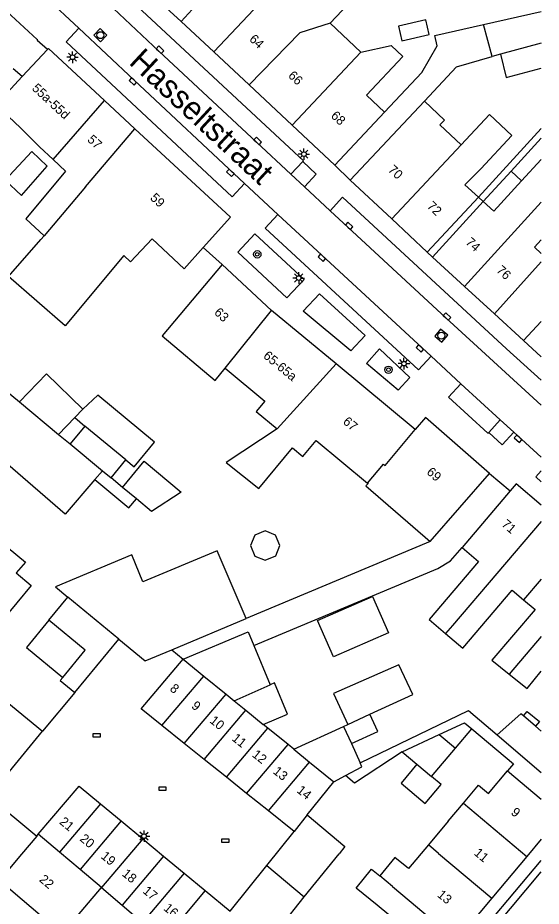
# Model space of a CAD drawing. Extents: x 132573 to 132944, y 398226 to 398676.
# Drawn here: x 132883.4 to 132940.1, y 398341.8 to 398438.1 of the extents above; entities that cross this region are included whole.
import ezdxf

# ---------------------------------------------------------------- set-up
doc = ezdxf.new("R2010")
doc.units = 0
for name, color, linetype in [('gg-afsc-erfafscheiding', 7, 'Continuous'), ('gg-afsc-hekwerk', 7, 'Continuous'), ('gg-afsc-muur', 7, 'Continuous'), ('gg-anno-huisnummerreeks BGT', 7, 'Continuous'), ('gg-anno-openbare ruimte label', 7, 'Continuous'), ('gg-bbg-bijgebouw', 7, 'Continuous'), ('gg-bbg-gedigitaliseerde bebouwing', 7, 'Continuous'), ('gg-bbg-gedigitaliseerde bebouwing onder overbouw', 7, 'Continuous'), ('gg-bbg-gedigitaliseerde bijgebouw', 7, 'Continuous'), ('gg-bbg-gedigitaliseerde overbouw', 7, 'Continuous'), ('gg-bbg-hoofdgebouw', 7, 'Continuous'), ('gg-bbg-luifel en loopbrug', 7, 'Continuous'), ('gg-bbg-pand overbouw', 7, 'Continuous'), ('gg-bbg-tussenscheiding', 7, 'Continuous'), ('gg-knt-verharding', 7, 'Continuous'), ('gg-knt-verharding nz', 7, 'Continuous'), ('gt-bbg-plantopografie pand', 7, 'Continuous'), ('gt-symb-boom', 7, 'Continuous'), ('gt-symb-kolk', 7, 'Continuous'), ('gt-symb-kolk center center', 7, 'Continuous'), ('gt-symb-lichtmast', 7, 'Continuous'), ('gt-symb-rioolschacht', 7, 'Continuous')]:
    doc.layers.add(name, color=color, linetype=linetype)

msp = doc.modelspace()

# ---------------------------------------------------------------- linework, layer by layer
at = {"layer": 'gg-afsc-erfafscheiding'}
for p, q in [((132933.304, 398418.624), (132940.113, 398426.079)), ((132936.851, 398421.461), (132940.113, 398425.032)), ((132928.09, 398381.331), (132908.172, 398372.976))]:
    msp.add_line(p, q, dxfattribs=at)
for points in [[(132923.154, 398427.841), (132927.189, 398432.136), (132928.845, 398435.01), (132928.603, 398436.147), (132933.873, 398437.331)], [(132927.46, 398429.034), (132930.944, 398432.75), (132934.814, 398433.88)], [(132863.045, 398395.109), (132866.966, 398391.729), (132867.783, 398392.696), (132884.262, 398379.11), (132883.243, 398377.928)], [(132908.987, 398370.064), (132928.905, 398378.419), (132930.304, 398379.226), (132931.543, 398380.683)], [(132920.514, 398357.346), (132932.24, 398363.01), (132935.33, 398360.377)], [(132932.583, 398361.056), (132937.101, 398357.264), (132936.459, 398356.498)], [(132925.064, 398358.538), (132919.898, 398355.166), (132918.925, 398355.982)]]:
    msp.add_lwpolyline(points, dxfattribs=at)
at = {"layer": 'gg-afsc-hekwerk'}
for p, q in [((132883.894, 398431.693), (132882.94, 398432.54)), ((132917.75, 398422.09), (132919.44, 398420.47)), ((132903.499, 398413.169), (132905.55, 398411.33))]:
    msp.add_line(p, q, dxfattribs=at)
at = {"layer": 'gg-afsc-muur'}
for p, q in [((132900.101, 398369.589), (132901.34, 398368.58)), ((132889.61, 398364.96), (132886.1, 398360.77))]:
    msp.add_line(p, q, dxfattribs=at)
at = {"layer": 'gg-bbg-bijgebouw'}
for p, q in [((132889.61, 398364.96), (132894.37, 398370.74)), ((132888.02, 398366.27), (132889.61, 398364.96)), ((132901.457, 398359.449), (132899.027, 398361.398)), ((132903.597, 398357.733), (132901.457, 398359.449)), ((132906.021, 398355.789), (132903.597, 398357.733)), ((132908.204, 398354.038), (132906.021, 398355.789)), ((132910.56, 398352.149), (132908.204, 398354.038)), ((132892.386, 398352.921), (132894.632, 398351.059)), ((132913.34, 398349.92), (132910.56, 398352.149)), ((132894.632, 398351.059), (132896.957, 398349.133)), ((132896.957, 398349.133), (132899.215, 398347.261)), ((132910.388, 398346.238), (132913.34, 398349.92)), ((132899.215, 398347.261), (132901.448, 398345.411)), ((132906.42, 398341.29), (132910.388, 398346.238)), ((132901.448, 398345.411), (132903.731, 398343.519)), ((132903.731, 398343.519), (132906.42, 398341.29))]:
    msp.add_line(p, q, dxfattribs=at)
for points in [[(132905.024, 398380.33), (132896.986, 398376.973), (132895.765, 398379.898), (132887.523, 398376.409), (132888.847, 398375.287)], [(132894.37, 398370.74), (132897.235, 398368.405), (132900.101, 398369.589)], [(132899.027, 398361.398), (132896.78, 398363.2), (132901.34, 398368.58)], [(132885.652, 398349.619), (132890.07, 398354.84), (132892.386, 398352.921)]]:
    msp.add_lwpolyline(points, dxfattribs=at)
at = {"layer": 'gg-bbg-gedigitaliseerde bebouwing'}
for p, q in [((132917.26, 398437.467), (132920.68, 398441.107)), ((132917.26, 398437.467), (132920.587, 398434.341)), ((132927.46, 398429.034), (132919.44, 398420.47)), ((132923.154, 398427.841), (132917.75, 398422.09)), ((132883.711, 398426.159), (132885.768, 398424.097)), ((132885.768, 398424.097), (132887.253, 398422.718)), ((132937.984, 398420.392), (132940.113, 398422.719)), ((132884.293, 398416.301), (132886.268, 398414.459)), ((132885.915, 398414.043), (132886.268, 398414.459)), ((132901.436, 398410.869), (132903.499, 398413.169)), ((132928.09, 398381.331), (132934.52, 398388.7)), ((132936.749, 398386.804), (132931.543, 398380.683)), ((132938.208, 398375.004), (132939.439, 398373.954)), ((132927.971, 398372.874), (132929.758, 398371.352)), ((132929.758, 398371.352), (132931.616, 398369.768)), ((132880.436, 398365.438), (132886.1, 398360.77)), ((132936.459, 398356.498), (132940.113, 398353.426)), ((132930.038, 398351.024), (132931.684, 398352.988)), ((132930.038, 398351.024), (132927.894, 398348.466)), ((132888.246, 398338.849), (132892.476, 398343.845))]:
    msp.add_line(p, q, dxfattribs=at)
for points in [[(132920.587, 398434.341), (132923.848, 398435.076), (132925.114, 398433.886), (132921.179, 398429.697), (132923.154, 398427.841)], [(132883.894, 398431.693), (132881.052, 398428.627), (132883.711, 398426.159)], [(132931.431, 398424.31), (132929.142, 398426.452), (132929.644, 398426.989), (132927.46, 398429.034)], [(132933.304, 398418.624), (132931.825, 398419.979), (132933.559, 398421.711), (132936.939, 398425.322), (132934.508, 398427.597), (132931.431, 398424.31)], [(132887.253, 398422.718), (132888.6, 398421.466), (132884.293, 398416.301)], [(132933.825, 398418.147), (132934.97, 398417.098), (132937.984, 398420.392)], [(132901.436, 398410.869), (132897.968, 398414.103), (132895.649, 398411.617), (132894.918, 398412.299), (132888.54, 398404.712), (132882.424, 398410.022), (132885.915, 398414.043)], [(132940.113, 398414.016), (132939.381, 398413.216), (132940.113, 398412.546)], [(132905.55, 398411.33), (132899.05, 398403.625), (132904.804, 398398.771), (132905.877, 398400.107)], [(132905.877, 398400.107), (132910.183, 398396.551), (132909.246, 398395.417), (132911.533, 398393.528)], [(132911.533, 398393.528), (132905.999, 398389.897), (132909.53, 398387.07), (132913.173, 398391.479), (132914.312, 398390.538), (132915.742, 398392.268), (132921.306, 398387.669)], [(132921.306, 398387.669), (132921.356, 398387.628), (132921.124, 398387.363), (132928.09, 398381.331)], [(132931.543, 398380.683), (132933.329, 398379.161), (132927.971, 398372.874)], [(132931.616, 398369.768), (132936.976, 398376.054), (132938.208, 398375.004)], [(132939.439, 398373.954), (132934.769, 398368.474), (132936.647, 398366.973)], [(132936.647, 398366.973), (132938.6, 398365.412), (132940.113, 398367.305)], [(132931.684, 398352.988), (132933.33, 398354.951), (132934.406, 398354.049), (132936.459, 398356.498)], [(132927.894, 398348.466), (132925.75, 398345.907), (132924.242, 398347.118), (132922.637, 398345.115)], [(132922.348, 398341.957), (132920.069, 398343.785), (132921.723, 398345.848), (132922.637, 398345.115)], [(132920.77, 398337.534), (132923.599, 398340.908), (132922.348, 398341.957)]]:
    msp.add_lwpolyline(points, dxfattribs=at)
at = {"layer": 'gg-bbg-gedigitaliseerde bebouwing onder overbouw'}
for p, q in [((132927.76, 398412.69), (132933.304, 398418.624)), ((132928.33, 398412.13), (132933.825, 398418.147))]:
    msp.add_line(p, q, dxfattribs=at)
at = {"layer": 'gg-bbg-gedigitaliseerde bijgebouw'}
for p, q in [((132933.873, 398437.331), (132940.113, 398438.728)), ((132934.814, 398433.88), (132933.873, 398437.331)), ((132940.113, 398435.305), (132935.71, 398434.121)), ((132935.71, 398434.121), (132934.814, 398433.88)), ((132889.588, 398394.748), (132890.488, 398395.682)), ((132887.849, 398392.941), (132889.588, 398394.748)), ((132890.695, 398393.832), (132889.102, 398391.905)), ((132895.126, 398390.166), (132890.695, 398393.832)), ((132887.849, 398392.941), (132889.102, 398391.905)), ((132893.532, 398388.24), (132895.126, 398390.166)), ((132894.778, 398387.198), (132893.532, 398388.24)), ((132908.172, 398372.976), (132905.024, 398380.33)), ((132886.805, 398372.807), (132888.847, 398375.287)), ((132900.101, 398369.589), (132908.172, 398372.976)), ((132908.987, 398370.064), (132910.77, 398365.813)), ((132888.02, 398366.27), (132888.292, 398366.601)), ((132917.616, 398364.862), (132919.158, 398361.509)), ((132937.913, 398362.669), (132935.33, 398360.377)), ((132938.182, 398362.44), (132937.913, 398362.669)), ((132939.49, 398361.326), (132938.182, 398362.44)), ((132910.523, 398361.1), (132910.015, 398361.514)), ((132912.692, 398359.333), (132910.523, 398361.1)), ((132913.317, 398358.824), (132918.698, 398361.298)), ((132918.698, 398361.298), (132919.158, 398361.509)), ((132940.113, 398360.795), (132939.49, 398361.326)), ((132925.064, 398358.538), (132929.071, 398360.418)), ((132929.071, 398360.418), (132930.815, 398358.952)), ((132935.33, 398360.377), (132940.113, 398356.302)), ((132913.317, 398358.824), (132912.692, 398359.333)), ((132919.554, 398359.436), (132920.514, 398357.346)), ((132928.23, 398355.877), (132930.815, 398358.952)), ((132925.064, 398358.538), (132926.647, 398357.208)), ((132917.65, 398355.295), (132918.925, 398355.982)), ((132914.774, 398351.708), (132917.65, 398355.295)), ((132914.457, 398342.827), (132918.217, 398347.516)), ((132892.476, 398343.845), (132894.719, 398341.948)), ((132910.008, 398337.28), (132914.457, 398342.827)), ((132894.719, 398341.948), (132896.932, 398340.075))]:
    msp.add_line(p, q, dxfattribs=at)
for points in [[(132925.01, 398435.572), (132927.985, 398436.257), (132927.62, 398437.841), (132924.646, 398437.156), (132925.01, 398435.572)], [(132890.488, 398395.682), (132886.533, 398399.49), (132883.608, 398396.451)], [(132891.771, 398388.035), (132888.559, 398384.309), (132876.639, 398394.585), (132880.479, 398399.04), (132883.608, 398396.451)], [(132894.778, 398387.198), (132897.114, 398390.025), (132901.104, 398386.685), (132897.901, 398384.584), (132896.279, 398385.941)], [(132891.771, 398388.035), (132895.461, 398384.964), (132896.279, 398385.941)], [(132910.211, 398382.49), (132909.085, 398382.016), (132908.623, 398380.884), (132909.097, 398379.757), (132910.229, 398379.296), (132911.355, 398379.77), (132911.817, 398380.901), (132911.343, 398382.028), (132910.211, 398382.49)], [(132883.243, 398377.928), (132884.878, 398376.579), (132881.764, 398372.802), (132879.522, 398374.651), (132880.633, 398375.999)], [(132888.292, 398366.601), (132890.737, 398369.569), (132886.805, 398372.807)], [(132901.34, 398368.58), (132908.372, 398371.53), (132908.987, 398370.064)], [(132921.559, 398362.613), (132926.2, 398364.747), (132924.71, 398367.986), (132917.616, 398364.862)], [(132910.015, 398361.514), (132912.649, 398362.619), (132911.225, 398366.013), (132910.77, 398365.813)], [(132919.554, 398359.436), (132922.414, 398360.751), (132921.559, 398362.613)], [(132918.925, 398355.982), (132920.702, 398356.939), (132920.514, 398357.346)], [(132926.647, 398357.208), (132924.929, 398355.164), (132927.547, 398352.963), (132929.265, 398355.007), (132928.23, 398355.877)], [(132914.774, 398351.708), (132918.843, 398348.296), (132918.217, 398347.516)]]:
    msp.add_lwpolyline(points, dxfattribs=at)
at = {"layer": 'gg-bbg-gedigitaliseerde overbouw'}
msp.add_line((132933.304, 398418.624), (132933.825, 398418.147), dxfattribs=at)
at = {"layer": 'gg-bbg-hoofdgebouw'}
for p, q in [((132897.465, 398441.015), (132901.114, 398437.654)), ((132901.114, 398437.654), (132904.67, 398434.38)), ((132886.627, 398434.629), (132883.894, 398431.693)), ((132886.74, 398434.75), (132886.627, 398434.629)), ((132892.835, 398429.094), (132886.74, 398434.75)), ((132904.67, 398434.38), (132908.492, 398430.789)), ((132908.492, 398430.789), (132913.143, 398426.419)), ((132896.113, 398426.052), (132892.835, 398429.094)), ((132913.143, 398426.419), (132917.75, 398422.09)), ((132896.113, 398426.052), (132906.45, 398416.46)), ((132919.44, 398420.47), (132923.919, 398416.282)), ((132906.45, 398416.46), (132903.499, 398413.169)), ((132923.919, 398416.282), (132927.76, 398412.69)), ((132931.816, 398408.942), (132928.33, 398412.13)), ((132910.89, 398406.35), (132905.55, 398411.33)), ((132935.049, 398405.985), (132931.816, 398408.942)), ((132917.889, 398400.569), (132910.89, 398406.35)), ((132938.208, 398403.096), (132935.049, 398405.985)), ((132940.113, 398401.353), (132938.208, 398403.096)), ((132926.47, 398393.48), (132917.889, 398400.569)), ((132880.35, 398353.8), (132886.1, 398360.77)), ((132885.477, 398349.412), (132883.843, 398347.481)), ((132885.477, 398349.412), (132885.652, 398349.619)), ((132940.113, 398349.08), (132938.559, 398347.225)), ((132883.843, 398347.481), (132881.424, 398344.622)), ((132938.559, 398347.225), (132934.77, 398342.704)), ((132934.77, 398342.704), (132930.949, 398338.146))]:
    msp.add_line(p, q, dxfattribs=at)
for points in [[(132934.52, 398388.7), (132927.58, 398394.75), (132926.47, 398393.48)], [(132940.113, 398385.259), (132937.4, 398387.57), (132936.749, 398386.804)]]:
    msp.add_lwpolyline(points, dxfattribs=at)
at = {"layer": 'gg-bbg-luifel en loopbrug'}
for p, q in [((132933.825, 398418.147), (132936.851, 398421.461)), ((132936.851, 398421.461), (132937.984, 398420.392)), ((132889.588, 398394.748), (132890.695, 398393.832)), ((132930.815, 398358.952), (132932.583, 398361.056))]:
    msp.add_line(p, q, dxfattribs=at)
for points in [[(132935.71, 398434.121), (132936.33, 398431.578), (132940.113, 398432.596)], [(132884.933, 398423.571), (132882.053, 398420.469), (132883.835, 398418.814), (132886.624, 398422), (132884.933, 398423.571)], [(132895.126, 398390.166), (132896.03, 398389.418), (132898.249, 398392.1), (132892.105, 398397.183), (132890.488, 398395.682)], [(132886.805, 398372.807), (132884.361, 398369.839), (132888.292, 398366.601)], [(132938.182, 398362.44), (132938.603, 398362.935), (132939.911, 398361.821), (132939.49, 398361.326)], [(132929.071, 398360.418), (132931.812, 398361.704), (132932.583, 398361.056)]]:
    msp.add_lwpolyline(points, dxfattribs=at)
at = {"layer": 'gg-bbg-pand overbouw'}
msp.add_line((132928.33, 398412.13), (132927.76, 398412.69), dxfattribs=at)
at = {"layer": 'gg-bbg-tussenscheiding'}
for p, q in [((132904.67, 398434.38), (132915.701, 398446.125)), ((132906.296, 398443.344), (132901.114, 398437.654)), ((132913.143, 398426.419), (132920.587, 398434.341)), ((132887.253, 398422.718), (132892.835, 398429.094)), ((132890.773, 398419.764), (132896.113, 398426.052)), ((132923.919, 398416.282), (132931.431, 398424.31)), ((132890.773, 398419.764), (132886.268, 398414.459)), ((132931.816, 398408.942), (132940.113, 398418.089)), ((132935.049, 398405.985), (132940.113, 398411.628)), ((132905.877, 398400.107), (132910.89, 398406.35)), ((132938.208, 398403.096), (132940.113, 398405.178)), ((132911.533, 398393.528), (132917.889, 398400.569)), ((132883.608, 398396.451), (132887.849, 398392.941)), ((132889.102, 398391.905), (132892.607, 398389.005)), ((132892.607, 398389.005), (132891.771, 398388.035)), ((132892.607, 398389.005), (132893.532, 398388.24)), ((132896.279, 398385.941), (132894.778, 398387.198)), ((132940.113, 398383.507), (132930.494, 398372.216)), ((132940.113, 398377.238), (132938.208, 398375.004)), ((132894.37, 398370.74), (132888.847, 398375.287)), ((132930.494, 398372.216), (132929.758, 398371.352)), ((132940.113, 398371.037), (132936.647, 398366.973)), ((132901.34, 398368.58), (132903.573, 398366.761)), ((132899.027, 398361.398), (132903.573, 398366.761)), ((132903.573, 398366.761), (132905.988, 398364.794)), ((132906.852, 398364.09), (132910.77, 398365.813)), ((132901.457, 398359.449), (132905.988, 398364.794)), ((132905.988, 398364.794), (132906.852, 398364.09)), ((132906.852, 398364.09), (132908.114, 398363.062)), ((132903.597, 398357.733), (132908.114, 398363.062)), ((132908.114, 398363.062), (132910.015, 398361.514)), ((132919.158, 398361.509), (132921.559, 398362.613)), ((132906.021, 398355.789), (132910.523, 398361.1)), ((132918.698, 398361.298), (132919.554, 398359.436)), ((132908.204, 398354.038), (132912.692, 398359.333)), ((132913.317, 398358.824), (132915.033, 398357.426)), ((132910.56, 398352.149), (132915.033, 398357.426)), ((132915.033, 398357.426), (132917.65, 398355.295)), ((132926.647, 398357.208), (132928.23, 398355.877)), ((132931.684, 398352.988), (132938.559, 398347.225)), ((132892.386, 398352.921), (132887.948, 398347.677)), ((132894.632, 398351.059), (132890.175, 398345.792)), ((132914.774, 398351.708), (132913.34, 398349.92)), ((132887.948, 398347.677), (132885.652, 398349.619)), ((132896.957, 398349.133), (132892.476, 398343.845)), ((132928.982, 398347.554), (132927.894, 398348.466)), ((132890.175, 398345.792), (132887.948, 398347.677)), ((132899.215, 398347.261), (132894.719, 398341.948)), ((132928.982, 398347.554), (132934.77, 398342.704)), ((132910.388, 398346.238), (132914.457, 398342.827)), ((132892.476, 398343.845), (132890.175, 398345.792)), ((132901.448, 398345.411), (132896.932, 398340.075)), ((132888.246, 398338.849), (132881.424, 398344.622)), ((132924.022, 398343.954), (132922.637, 398345.115)), ((132903.731, 398343.519), (132899.196, 398338.16)), ((132924.022, 398343.954), (132930.949, 398338.146))]:
    msp.add_line(p, q, dxfattribs=at)
for points in [[(132917.26, 398437.467), (132913.968, 398436.418), (132908.492, 398430.789)], [(132921.306, 398387.669), (132923.023, 398389.705), (132923.2, 398389.556), (132926.47, 398393.48)]]:
    msp.add_lwpolyline(points, dxfattribs=at)
at = {"layer": 'gg-knt-verharding'}
for p, q in [((132885.643, 398441.063), (132890.02, 398436.944)), ((132914.284, 398422.48), (132913.002, 398421.114)), ((132914.284, 398422.48), (132915.738, 398421.122)), ((132913.002, 398421.114), (132914.487, 398419.734)), ((132915.738, 398421.122), (132914.487, 398419.734)), ((132907.978, 398420.122), (132911.603, 398416.756)), ((132914.487, 398419.734), (132917.273, 398417.146)), ((132928.182, 398401.404), (132911.603, 398416.756)), ((132928.182, 398401.404), (132931.423, 398398.421)), ((132931.423, 398398.421), (132935.672, 398394.511)), ((132934.429, 398393.149), (132935.672, 398394.511)), ((132935.672, 398394.511), (132937.14, 398393.16)), ((132937.14, 398393.16), (132940.113, 398390.466)), ((132934.52, 398388.7), (132936.749, 398386.804)), ((132933.079, 398337.157), (132940.113, 398345.536))]:
    msp.add_line(p, q, dxfattribs=at)
for points in [[(132886.627, 398434.629), (132885.53, 398435.616), (132885.581, 398435.671), (132885.532, 398435.717), (132879.866, 398440.959)], [(132891.944, 398440.824), (132898.699, 398434.461), (132909.279, 398424.572), (132913.002, 398421.114)], [(132890.02, 398436.944), (132896.022, 398431.296), (132907.978, 398420.122)], [(132940.113, 398396.101), (132929.776, 398405.567), (132917.273, 398417.146)], [(132912.559, 398407.719), (132907.252, 398412.68), (132909.093, 398414.676), (132914.436, 398409.728), (132912.559, 398407.719)], [(132914.342, 398406.279), (132916.116, 398408.161), (132921.038, 398403.633), (132919.501, 398401.985), (132914.342, 398406.279)], [(132921.179, 398400.626), (132922.593, 398402.192), (132925.896, 398399.108), (132924.636, 398397.735), (132921.179, 398400.626)], [(132934.429, 398393.149), (132935.884, 398391.799), (132937.14, 398393.16)], [(132880.35, 398353.8), (132880.276, 398353.71), (132885.477, 398349.412)]]:
    msp.add_lwpolyline(points, dxfattribs=at)
at = {"layer": 'gg-knt-verharding nz'}
msp.add_line((132906.636, 398418.658), (132907.978, 398420.122), dxfattribs=at)
for points in [[(132893.233, 398442.169), (132893.303, 398442.226), (132914.365, 398422.567), (132914.284, 398422.48)], [(132890.02, 398436.944), (132888.658, 398435.462), (132906.636, 398418.658)], [(132940.113, 398398.799), (132936.37, 398402.199), (132918.582, 398418.621), (132917.273, 398417.146)], [(132928.182, 398401.404), (132926.815, 398399.945), (132910.235, 398415.268), (132911.603, 398416.756)], [(132931.423, 398398.421), (132930.075, 398396.955), (132934.328, 398393.055), (132934.429, 398393.149)], [(132940.113, 398388.989), (132939.527, 398388.327), (132940.113, 398387.8)], [(132929.318, 398332.677), (132928.683, 398333.209), (132940.113, 398346.771)]]:
    msp.add_lwpolyline(points, dxfattribs=at)
at = {"layer": 'gt-bbg-plantopografie pand'}
msp.add_lwpolyline([(132923.572, 398371.441), (132917.622, 398368.825), (132915.891, 398372.761), (132921.841, 398375.377), (132923.572, 398371.441)], dxfattribs=at)
at = {"layer": 'gt-symb-boom'}
for centre, radius in [((132909.364, 398412.44), 0.4), ((132909.364, 398412.44), 0.2), ((132923.573, 398399.937), 0.4), ((132923.573, 398399.937), 0.2)]:
    msp.add_circle(centre, radius, dxfattribs=at)
at = {"layer": 'gt-symb-kolk'}
for points in [[(132898.699, 398434.461), (132898.972, 398434.204), (132899.246, 398434.495), (132898.7, 398435.009), (132898.426, 398434.718), (132898.699, 398434.461)], [(132896.022, 398431.296), (132895.749, 398431.553), (132895.475, 398431.262), (132896.021, 398430.748), (132896.295, 398431.039), (132896.022, 398431.296)], [(132909.279, 398424.572), (132909.553, 398424.316), (132909.826, 398424.608), (132909.278, 398425.12), (132909.005, 398424.828), (132909.279, 398424.572)], [(132906.578, 398421.422), (132906.304, 398421.678), (132906.031, 398421.386), (132906.579, 398420.874), (132906.852, 398421.166), (132906.578, 398421.422)], [(132919.177, 398415.377), (132919.452, 398415.122), (132919.724, 398415.415), (132919.174, 398415.925), (132918.902, 398415.632), (132919.177, 398415.377)], [(132916.488, 398412.221), (132916.213, 398412.476), (132915.941, 398412.183), (132916.491, 398411.673), (132916.763, 398411.966), (132916.488, 398412.221)], [(132929.776, 398405.567), (132930.051, 398405.312), (132930.323, 398405.606), (132929.772, 398406.115), (132929.501, 398405.822), (132929.776, 398405.567)], [(132927.101, 398402.399), (132926.826, 398402.654), (132926.554, 398402.36), (132927.105, 398401.851), (132927.376, 398402.144), (132927.101, 398402.399)], [(132937.743, 398392.605), (132937.467, 398392.859), (132937.196, 398392.565), (132937.748, 398392.057), (132938.019, 398392.351), (132937.743, 398392.605)]]:
    msp.add_lwpolyline(points, dxfattribs=at)
at = {"layer": 'gt-symb-kolk center center'}
for points in [[(132891.597, 398360.524), (132892.347, 398360.524), (132892.347, 398360.124), (132891.597, 398360.124)], [(132898.723, 398354.746), (132899.473, 398354.746), (132899.473, 398354.346), (132898.723, 398354.346)], [(132905.542, 398349.137), (132906.292, 398349.137), (132906.292, 398348.737), (132905.542, 398348.737)]]:
    msp.add_lwpolyline(points, close=True, dxfattribs=at)
at = {"layer": 'gt-symb-lichtmast'}
for p, q in [((132889.181, 398433.967), (132888.916, 398434.232)), ((132889.358, 398434.04), (132889.358, 398434.415)), ((132889.535, 398433.967), (132889.8, 398434.232)), ((132889.108, 398433.79), (132888.733, 398433.79)), ((132889.181, 398433.613), (132888.916, 398433.348)), ((132889.358, 398433.54), (132889.358, 398433.165)), ((132889.8, 398433.348), (132889.535, 398433.613)), ((132889.608, 398433.79), (132889.983, 398433.79)), ((132914.161, 398423.29), (132913.786, 398423.29)), ((132914.234, 398423.467), (132913.969, 398423.732)), ((132914.411, 398423.54), (132914.411, 398423.915)), ((132914.588, 398423.467), (132914.853, 398423.732)), ((132914.661, 398423.29), (132915.036, 398423.29)), ((132914.234, 398423.113), (132913.969, 398422.848)), ((132914.411, 398423.04), (132914.411, 398422.665)), ((132914.853, 398422.848), (132914.588, 398423.113)), ((132913.596, 398409.873), (132913.221, 398409.873)), ((132913.669, 398410.05), (132913.404, 398410.315)), ((132913.846, 398410.123), (132913.846, 398410.498)), ((132914.023, 398410.05), (132914.288, 398410.315)), ((132914.096, 398409.873), (132914.471, 398409.873)), ((132913.669, 398409.696), (132913.404, 398409.431)), ((132913.846, 398409.623), (132913.846, 398409.248)), ((132914.288, 398409.431), (132914.023, 398409.696)), ((132925.242, 398400.848), (132925.242, 398401.223)), ((132924.992, 398400.598), (132924.617, 398400.598)), ((132925.065, 398400.775), (132924.8, 398401.04)), ((132925.065, 398400.421), (132924.8, 398400.156)), ((132925.242, 398400.348), (132925.242, 398399.973)), ((132925.419, 398400.775), (132925.684, 398401.04)), ((132925.684, 398400.156), (132925.419, 398400.421)), ((132925.492, 398400.598), (132925.867, 398400.598)), ((132896.846, 398349.415), (132896.471, 398349.415)), ((132896.919, 398349.592), (132896.654, 398349.857)), ((132896.919, 398349.238), (132896.654, 398348.973)), ((132897.096, 398349.665), (132897.096, 398350.04)), ((132897.096, 398349.165), (132897.096, 398348.79)), ((132897.273, 398349.592), (132897.538, 398349.857)), ((132897.538, 398348.973), (132897.273, 398349.238)), ((132897.346, 398349.415), (132897.721, 398349.415))]:
    msp.add_line(p, q, dxfattribs=at)
for centre in [(132889.358, 398433.79), (132914.411, 398423.29), (132913.846, 398409.873), (132925.242, 398400.598), (132897.096, 398349.415)]:
    msp.add_circle(centre, 0.25, dxfattribs=at)
at = {"layer": 'gt-symb-rioolschacht'}
for points in [[(132891.664, 398436.168), (132892.382, 398435.472), (132893.078, 398436.19), (132892.36, 398436.886)], [(132929.216, 398404.334), (132928.581, 398403.561), (132929.354, 398402.926), (132929.989, 398403.699)]]:
    msp.add_lwpolyline(points, close=True, dxfattribs=at)
for centre in [(132892.371, 398436.179), (132929.285, 398403.63)]:
    msp.add_circle(centre, 0.375, dxfattribs=at)

# ---------------------------------------------------------------- texts
at = {"layer": 'gg-anno-huisnummerreeks BGT'}
for s, rotation, p in [('64', 316.8, (132908.424, 398435.656)), ('66', 316.8, (132912.632, 398431.702)), ('55a-55d', 317.1, (132884.89, 398430.33)), ('68', 316.8, (132917.26, 398427.353)), ('57', 317.1, (132890.883, 398424.766)), ('70', 316.9, (132923.46, 398421.503)), ('59', 317.1, (132897.688, 398418.453)), ('72', 316.9, (132927.674, 398417.563)), ('74', 317.6, (132931.855, 398413.649)), ('76', 317.6, (132935.179, 398410.609)), ('63', 317, (132904.619, 398406.045)), ('65-65a', 320.4, (132909.932, 398401.308)), ('67', 320.4, (132918.56, 398394.18)), ('69', 318.9, (132927.627, 398388.739)), ('71', 319.6, (132935.737, 398383.074)), ('8', 321.3, (132899.814, 398365.253)), ('9', 321.3, (132902.153, 398363.378)), ('10', 321.3, (132904.136, 398361.787)), ('11', 321.3, (132906.534, 398359.864)), ('12', 321.3, (132908.725, 398358.106)), ('13', 321.3, (132910.99, 398356.29)), ('14', 321.3, (132913.559, 398354.229)), ('9', 320.1, (132936.758, 398351.86)), ('21', 320.4, (132887.858, 398350.828)), ('20', 320.3, (132890.065, 398349.001)), ('19', 320.4, (132892.349, 398347.106)), ('11', 320.1, (132932.76, 398347.463)), ('18', 320.3, (132894.64, 398345.209)), ('22', 319.7, (132885.672, 398344.594)), ('17', 320.4, (132896.887, 398343.346)), ('13', 320.1, (132928.773, 398342.936)), ('16', 320.4, (132899.144, 398341.475))]:
    msp.add_text(s, height=1, rotation=rotation, dxfattribs=at).set_placement(p)
at = {"layer": 'gg-anno-openbare ruimte label'}
msp.add_text('Hasseltstraat', height=2.5, rotation=317.1, dxfattribs=at).set_placement((132895.358, 398433.131))

doc.saveas('drawing.dxf')
